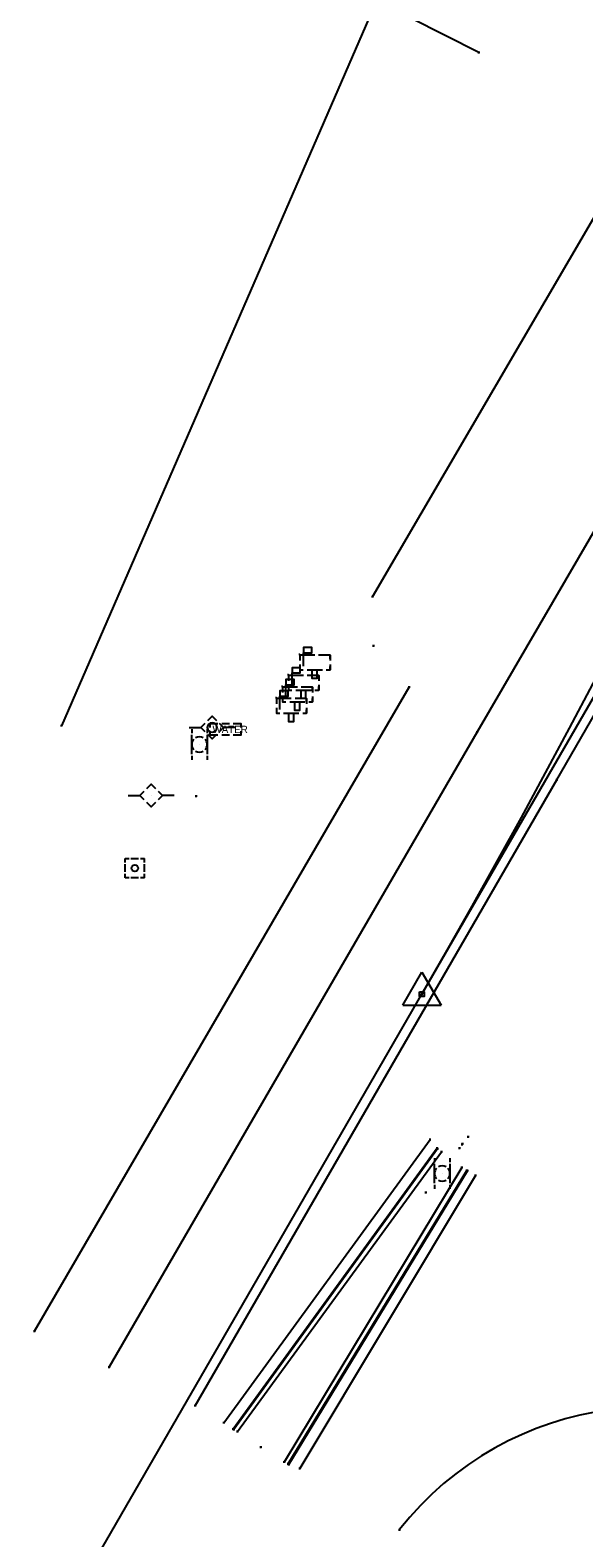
# Model space of a CAD drawing. Extents: x 1954856 to 2011933, y 399149 to 426294.
# Drawn here: x 2006044 to 2006116.2, y 401293.2 to 401490.1 of the extents above; entities that cross this region are included whole.
import ezdxf

# ---------------------------------------------------------------- set-up
doc = ezdxf.new("R2010")
doc.units = 0
for name, color, linetype in [('BaselineSurvey', 7, 'Continuous'), ('CGBack_ep', 7, 'Continuous'), ('CGep_ep', 7, 'Continuous'), ('CGFace_ep', 7, 'Continuous'), ('DelineatorPost_ep', 7, 'Continuous'), ('Driveway_ep', 7, 'Continuous'), ('Fence_ep', 7, 'Continuous'), ('Mailbox_ep', 7, 'Continuous'), ('MeterWater_ep', 7, 'Continuous'), ('MonumentNL_ep', 7, 'Continuous'), ('PavtAsphalt_ep', 7, 'Continuous'), ('PMRK_ep', 7, 'Continuous'), ('PointLocator_ep', 7, 'Continuous'), ('PoleElec_ep', 7, 'Continuous'), ('PoleShared_ep', 7, 'Continuous'), ('ShldrPaved_ep', 7, 'Continuous'), ('TelePed_ep', 7, 'Continuous')]:
    doc.layers.add(name, color=color, linetype=linetype)

# ---------------------------------------------------------------- blocks, each defined once
blk = doc.blocks.new('SURVPN-CROSS-')
at = {"layer": 'PointLocator_ep'}
for p, q in [((0.125, 0), (-0.125, 0)), ((0, -0.125), (0, 0.125)), ((0, 0), (0, 0))]:
    blk.add_line(p, q, dxfattribs=at)

msp = doc.modelspace()

# ---------------------------------------------------------------- linework, layer by layer
at = {"layer": 'BaselineSurvey'}
msp.add_line((2004815.66, 399148.96), (2006095.1, 401364.22), dxfattribs=at)
msp.add_line((2004815.66, 399148.96), (2006095.1, 401364.22), dxfattribs=at)
msp.add_lwpolyline([(2006095.1, 401364.22), (2006751.44, 402500.64), (2007687.69, 404121.69)], dxfattribs=at)
msp.add_arc((2005102.8, 401937.33), 1145.91, 329.99111, 11.93882, dxfattribs=at)
msp.add_arc((2005102.8, 401937.33), 1145.91, 329.99111, 11.93882, dxfattribs=at)
at = {"layer": 'CGBack_ep'}
for p, q in [((2006071.03, 401307.12), (2006097.64, 401343.62)), ((2006100.32, 401341.58), (2006077.12, 401303.14))]:
    msp.add_line(p, q, dxfattribs=at)
at = {"layer": 'CGep_ep'}
for p, q in [((2006097.07, 401344.11), (2006070.46, 401307.45)), ((2006077.75, 401302.84), (2006101.04, 401341.18))]:
    msp.add_line(p, q, dxfattribs=at)
at = {"layer": 'CGFace_ep'}
for p, q in [((2006097.12, 401344.03), (2006070.54, 401307.39)), ((2006077.66, 401302.89), (2006100.94, 401341.2))]:
    msp.add_line(p, q, dxfattribs=at)
at = {"layer": 'DelineatorPost_ep'}
for p, q in [((2006065.07, 401398.82), (2006065.07, 401398.32)), ((2006065.07, 401395.57), (2006065.07, 401398.07)), ((2006067.07, 401398.82), (2006067.07, 401398.32)), ((2006067.07, 401398.07), (2006067.07, 401395.57)), ((2006066.07, 401396.82), (2006066.07, 401396.82)), ((2006065.07, 401395.32), (2006065.07, 401394.82)), ((2006067.07, 401395.32), (2006067.07, 401394.82)), ((2006096.74, 401342.81), (2006096.74, 401342.31)), ((2006098.74, 401342.81), (2006098.74, 401342.31)), ((2006096.74, 401339.56), (2006096.74, 401342.06)), ((2006097.74, 401340.81), (2006097.74, 401340.81)), ((2006098.74, 401342.06), (2006098.74, 401339.56)), ((2006096.74, 401339.31), (2006096.74, 401338.81)), ((2006098.74, 401339.31), (2006098.74, 401338.81))]:
    msp.add_line(p, q, dxfattribs=at)
for centre, start, end in [((2006066.07, 401396.82), 60, 120), ((2006066.07, 401396.82), 138.5904, 221.4096), ((2006066.07, 401396.82), 240, 300), ((2006066.07, 401396.82), 318.5904, 41.4096), ((2006097.74, 401340.81), 138.5904, 221.4096), ((2006097.74, 401340.81), 60, 120), ((2006097.74, 401340.81), 318.5904, 41.4096), ((2006097.74, 401340.81), 240, 300)]:
    msp.add_arc(centre, 1, start, end, dxfattribs=at)
at = {"layer": 'Driveway_ep'}
msp.add_line((2006088.65, 401416.12), (2006131.95, 401490.32), dxfattribs=at)
at = {"layer": 'Fence_ep'}
msp.add_lwpolyline([(2006102.53, 401487.15), (2006089.17, 401493.91), (2006048.05, 401399.27)], dxfattribs=at)
at = {"layer": 'Mailbox_ep'}
for p, q in [((2006079.16, 401408.47), (2006079.16, 401407.77)), ((2006081.11, 401408.47), (2006079.16, 401408.47)), ((2006079.63, 401407.06), (2006079.63, 401408.79)), ((2006079.63, 401408.79), (2006080.61, 401408.79)), ((2006083.11, 401408.47), (2006083.11, 401407.77)), ((2006077.69, 401405.84), (2006077.69, 401405.13)), ((2006079.64, 401405.84), (2006077.69, 401405.84)), ((2006078.15, 401404.42), (2006078.15, 401406.16)), ((2006078.15, 401406.16), (2006079.14, 401406.16)), ((2006080.11, 401406.56), (2006080.61, 401406.56)), ((2006080.61, 401406.56), (2006082.11, 401406.56)), ((2006081.64, 401405.84), (2006081.64, 401405.13)), ((2006083.11, 401407.27), (2006083.11, 401406.56)), ((2006076.89, 401404.3), (2006076.89, 401403.6)), ((2006078.84, 401404.3), (2006076.89, 401404.3)), ((2006077.35, 401402.89), (2006077.35, 401404.62)), ((2006077.35, 401404.62), (2006078.34, 401404.62)), ((2006078.64, 401403.92), (2006079.14, 401403.92)), ((2006079.14, 401403.92), (2006080.64, 401403.92)), ((2006080.84, 401404.3), (2006080.84, 401403.6)), ((2006081.1, 401405.48), (2006081.1, 401405.48)), ((2006081.64, 401404.63), (2006081.64, 401403.92)), ((2006076.1, 401402.82), (2006076.1, 401402.11)), ((2006078.05, 401402.82), (2006076.1, 401402.82)), ((2006076.56, 401401.4), (2006076.56, 401403.14)), ((2006076.56, 401403.14), (2006077.55, 401403.14)), ((2006077.84, 401402.39), (2006078.34, 401402.39)), ((2006078.34, 401402.39), (2006079.84, 401402.39)), ((2006079.62, 401402.85), (2006079.62, 401402.85)), ((2006080.05, 401402.82), (2006080.05, 401402.11)), ((2006080.84, 401403.1), (2006080.84, 401402.39)), ((2006077.05, 401400.91), (2006077.55, 401400.91)), ((2006077.55, 401400.91), (2006079.05, 401400.91)), ((2006078.04, 401399.83), (2006078.04, 401399.83)), ((2006078.82, 401401.31), (2006078.82, 401401.31)), ((2006080.05, 401401.61), (2006080.05, 401400.91))]:
    msp.add_line(p, q, dxfattribs=at)
for points in [[(2006079.05, 401408.6), (2006079.13, 401408.6), (2006079.16, 401408.42)], [(2006080.61, 401409.48), (2006079.63, 401409.48), (2006079.63, 401408.79)], [(2006080.61, 401408.79), (2006080.71, 401408.79), (2006080.71, 401409.48), (2006080.61, 401409.48)], [(2006083.11, 401408.01), (2006083.11, 401408.47), (2006081.61, 401408.47)], [(2006077.57, 401405.96), (2006077.65, 401405.96), (2006077.69, 401405.79)], [(2006079.14, 401406.85), (2006078.15, 401406.85), (2006078.15, 401406.16)], [(2006079.14, 401406.16), (2006079.23, 401406.16), (2006079.23, 401406.85), (2006079.14, 401406.85)], [(2006079.16, 401407.27), (2006079.16, 401406.56), (2006079.61, 401406.56)], [(2006081.64, 401405.38), (2006081.64, 401405.84), (2006080.14, 401405.84)], [(2006080.75, 401406.56), (2006080.75, 401405.48), (2006081.44, 401405.48), (2006081.44, 401406.56)], [(2006082.61, 401406.56), (2006083.11, 401406.56), (2006083.11, 401407.01)], [(2006077.55, 401403.83), (2006076.56, 401403.83), (2006076.56, 401403.14)], [(2006076.78, 401404.43), (2006076.86, 401404.43), (2006076.89, 401404.25)], [(2006078.34, 401405.31), (2006077.35, 401405.31), (2006077.35, 401404.62)], [(2006077.55, 401403.14), (2006077.64, 401403.14), (2006077.64, 401403.83), (2006077.55, 401403.83)], [(2006077.69, 401404.63), (2006077.69, 401403.92), (2006078.14, 401403.92)], [(2006078.34, 401404.62), (2006078.43, 401404.62), (2006078.43, 401405.31), (2006078.34, 401405.31)], [(2006079.28, 401403.92), (2006079.28, 401402.85), (2006079.97, 401402.85), (2006079.97, 401403.92)], [(2006080.84, 401403.84), (2006080.84, 401404.3), (2006079.34, 401404.3)], [(2006081.14, 401403.92), (2006081.64, 401403.92), (2006081.64, 401404.38)], [(2006075.99, 401402.95), (2006076.07, 401402.95), (2006076.1, 401402.77)], [(2006076.89, 401403.1), (2006076.89, 401402.39), (2006077.34, 401402.39)], [(2006078.48, 401402.39), (2006078.48, 401401.31), (2006079.17, 401401.31), (2006079.17, 401402.39)], [(2006080.05, 401402.36), (2006080.05, 401402.82), (2006078.55, 401402.82)], [(2006080.34, 401402.39), (2006080.84, 401402.39), (2006080.84, 401402.84)], [(2006076.1, 401401.61), (2006076.1, 401400.91), (2006076.55, 401400.91)], [(2006077.69, 401400.91), (2006077.69, 401399.83), (2006078.38, 401399.83), (2006078.38, 401400.91)], [(2006079.55, 401400.91), (2006080.05, 401400.91), (2006080.05, 401401.36)]]:
    msp.add_lwpolyline(points, dxfattribs=at)
at = {"layer": 'MeterWater_ep'}
msp.add_line((2006069.47, 401398.79), (2006069.47, 401398.79), dxfattribs=at)
for points in [[(2006067.47, 401399.04), (2006067.47, 401399.54), (2006068.47, 401399.54)], [(2006068.47, 401398.04), (2006067.47, 401398.04), (2006067.47, 401398.54)], [(2006068.97, 401399.54), (2006069.97, 401399.54)], [(2006069.97, 401398.04), (2006068.97, 401398.04)], [(2006070.47, 401399.54), (2006071.47, 401399.54), (2006071.47, 401399.04)], [(2006071.47, 401398.54), (2006071.47, 401398.04), (2006070.47, 401398.04)]]:
    msp.add_lwpolyline(points, dxfattribs=at)
at = {"layer": 'MonumentNL_ep'}
for p, q in [((2006092.59, 401362.78), (2006095.09, 401367.11)), ((2006095.09, 401367.11), (2006097.59, 401362.78)), ((2006092.59, 401362.78), (2006097.59, 401362.78)), ((2006095.09, 401364.22), (2006095.09, 401364.22))]:
    msp.add_line(p, q, dxfattribs=at)
msp.add_lwpolyline([(2006094.79, 401364.52), (2006095.39, 401364.52), (2006095.39, 401363.92), (2006094.79, 401363.92)], close=True, dxfattribs=at)
at = {"layer": 'PavtAsphalt_ep'}
for p, q in [((2006069.24, 401308.28), (2006096.16, 401345.25)), ((2006102.07, 401340.55), (2006079.15, 401302.29))]:
    msp.add_line(p, q, dxfattribs=at)
msp.add_lwpolyline([(2006054.29, 401315.52), (2006102.3, 401398.42), (2006149.97, 401480.37), (2006190, 401548.85), (2006229.29, 401617.08), (2006237.48, 401631.06)], dxfattribs=at)
msp.add_arc((2006125.11, 401268.41), 41.91, 53.2441, 141.8601, dxfattribs=at)
at = {"layer": 'PMRK_ep'}
msp.add_lwpolyline([(2006065.53, 401310.49), (2006112.72, 401392.19), (2006160.25, 401474.61), (2006200.54, 401543.09), (2006235.51, 401603.67)], dxfattribs=at)
at = {"layer": 'PointLocator_ep'}
for p, q in [((2006102.65, 401487.15), (2006102.4, 401487.15)), ((2006102.53, 401487.02), (2006102.53, 401487.27)), ((2006102.53, 401487.15), (2006102.53, 401487.15)), ((2006088.77, 401416.12), (2006088.52, 401416.12)), ((2006088.65, 401415.99), (2006088.65, 401416.24)), ((2006088.65, 401416.12), (2006088.65, 401416.12)), ((2006088.92, 401409.7), (2006088.67, 401409.7)), ((2006088.79, 401409.57), (2006088.79, 401409.82)), ((2006088.79, 401409.7), (2006088.79, 401409.7)), ((2006093.57, 401404.31), (2006093.32, 401404.31)), ((2006093.44, 401404.19), (2006093.44, 401404.44)), ((2006093.44, 401404.31), (2006093.44, 401404.31)), ((2006048.17, 401399.27), (2006047.92, 401399.27)), ((2006048.05, 401399.15), (2006048.05, 401399.4)), ((2006048.05, 401399.27), (2006048.05, 401399.27)), ((2006102.42, 401398.42), (2006102.17, 401398.42)), ((2006102.3, 401398.3), (2006102.3, 401398.55)), ((2006102.3, 401398.42), (2006102.3, 401398.42)), ((2006112.85, 401392.19), (2006112.6, 401392.19)), ((2006112.72, 401392.07), (2006112.72, 401392.32)), ((2006112.72, 401392.19), (2006112.72, 401392.19)), ((2006065.75, 401390.08), (2006065.5, 401390.08)), ((2006065.62, 401389.96), (2006065.62, 401390.21)), ((2006065.62, 401390.08), (2006065.62, 401390.08)), ((2006095.1, 401364.1), (2006095.1, 401364.35)), ((2006095.22, 401364.22), (2006094.97, 401364.22)), ((2006095.1, 401364.22), (2006095.1, 401364.22)), ((2006096.28, 401345.25), (2006096.03, 401345.25)), ((2006096.16, 401345.13), (2006096.16, 401345.38)), ((2006096.16, 401345.25), (2006096.16, 401345.25)), ((2006100.51, 401344.69), (2006100.26, 401344.69)), ((2006100.39, 401344.56), (2006100.39, 401344.81)), ((2006100.39, 401344.69), (2006100.39, 401344.69)), ((2006101.26, 401345.6), (2006101.01, 401345.6)), ((2006101.13, 401345.48), (2006101.13, 401345.73)), ((2006101.13, 401345.6), (2006101.13, 401345.6)), ((2006097.19, 401344.11), (2006096.94, 401344.11)), ((2006097.07, 401343.99), (2006097.07, 401344.24)), ((2006097.07, 401344.11), (2006097.07, 401344.11)), ((2006097.76, 401343.62), (2006097.51, 401343.62)), ((2006097.64, 401343.5), (2006097.64, 401343.75)), ((2006097.64, 401343.62), (2006097.64, 401343.62)), ((2006100.11, 401344.12), (2006099.86, 401344.12)), ((2006099.99, 401344), (2006099.99, 401344.25)), ((2006099.99, 401344.12), (2006099.99, 401344.12)), ((2006100.44, 401341.58), (2006100.19, 401341.58)), ((2006100.32, 401341.45), (2006100.32, 401341.7)), ((2006100.32, 401341.58), (2006100.32, 401341.58)), ((2006101.17, 401341.18), (2006100.92, 401341.18)), ((2006101.04, 401341.06), (2006101.04, 401341.31)), ((2006101.04, 401341.18), (2006101.04, 401341.18)), ((2006102.2, 401340.55), (2006101.95, 401340.55)), ((2006102.07, 401340.42), (2006102.07, 401340.67)), ((2006102.07, 401340.55), (2006102.07, 401340.55)), ((2006095.73, 401338.33), (2006095.48, 401338.33)), ((2006095.6, 401338.21), (2006095.6, 401338.46)), ((2006095.6, 401338.33), (2006095.6, 401338.33)), ((2006044.68, 401320.23), (2006044.43, 401320.23)), ((2006044.56, 401320.11), (2006044.56, 401320.36)), ((2006044.56, 401320.23), (2006044.56, 401320.23)), ((2006054.41, 401315.52), (2006054.16, 401315.52)), ((2006054.29, 401315.4), (2006054.29, 401315.65)), ((2006054.29, 401315.52), (2006054.29, 401315.52)), ((2006065.66, 401310.49), (2006065.41, 401310.49)), ((2006065.53, 401310.37), (2006065.53, 401310.62)), ((2006065.53, 401310.49), (2006065.53, 401310.49)), ((2006069.36, 401308.28), (2006069.11, 401308.28)), ((2006069.24, 401308.15), (2006069.24, 401308.4)), ((2006069.24, 401308.28), (2006069.24, 401308.28)), ((2006070.59, 401307.45), (2006070.34, 401307.45)), ((2006070.46, 401307.33), (2006070.46, 401307.58)), ((2006070.46, 401307.45), (2006070.46, 401307.45)), ((2006071.03, 401306.99), (2006071.03, 401307.24)), ((2006071.15, 401307.12), (2006070.9, 401307.12)), ((2006071.03, 401307.12), (2006071.03, 401307.12)), ((2006074.21, 401305.09), (2006073.96, 401305.09)), ((2006074.08, 401304.97), (2006074.08, 401305.22)), ((2006074.08, 401305.09), (2006074.08, 401305.09)), ((2006077.25, 401303.14), (2006077, 401303.14)), ((2006077.12, 401303.02), (2006077.12, 401303.27)), ((2006077.12, 401303.14), (2006077.12, 401303.14)), ((2006077.88, 401302.84), (2006077.62, 401302.84)), ((2006077.75, 401302.71), (2006077.75, 401302.96)), ((2006077.75, 401302.84), (2006077.75, 401302.84)), ((2006079.27, 401302.29), (2006079.02, 401302.29)), ((2006079.15, 401302.17), (2006079.15, 401302.42)), ((2006079.15, 401302.29), (2006079.15, 401302.29)), ((2006092.28, 401294.3), (2006092.03, 401294.3)), ((2006092.15, 401294.17), (2006092.15, 401294.42)), ((2006092.15, 401294.3), (2006092.15, 401294.3))]:
    msp.add_line(p, q, dxfattribs=at)
at = {"layer": 'PoleElec_ep'}
for p, q in [((2006056.77, 401390.15), (2006058.27, 401390.15)), ((2006058.27, 401390.15), (2006058.84, 401390.72)), ((2006058.84, 401389.58), (2006058.27, 401390.15)), ((2006059.76, 401390.15), (2006059.76, 401390.15)), ((2006062.75, 401390.15), (2006061.25, 401390.15))]:
    msp.add_line(p, q, dxfattribs=at)
for points in [[(2006059.19, 401391.07), (2006059.76, 401391.64), (2006060.33, 401391.07)], [(2006060.68, 401390.72), (2006061.25, 401390.15), (2006060.68, 401389.58)], [(2006060.33, 401389.23), (2006059.76, 401388.66), (2006059.19, 401389.23)]]:
    msp.add_lwpolyline(points, dxfattribs=at)
at = {"layer": 'PoleShared_ep'}
for p, q in [((2006064.74, 401399.04), (2006066.24, 401399.04)), ((2006066.24, 401399.04), (2006066.8, 401399.6)), ((2006066.8, 401398.48), (2006066.24, 401399.04)), ((2006067.72, 401399.04), (2006067.72, 401399.04)), ((2006070.71, 401399.04), (2006069.21, 401399.04))]:
    msp.add_line(p, q, dxfattribs=at)
for points in [[(2006067.16, 401399.96), (2006067.72, 401400.53), (2006068.29, 401399.96)], [(2006068.29, 401398.12), (2006067.72, 401397.55), (2006067.16, 401398.12)], [(2006068.65, 401399.6), (2006069.21, 401399.04), (2006068.64, 401398.47)]]:
    msp.add_lwpolyline(points, dxfattribs=at)
for start, end in [(90, 270), (270, 90)]:
    msp.add_arc((2006067.72, 401399.04), 0.625, start, end, dxfattribs=at)
at = {"layer": 'ShldrPaved_ep'}
msp.add_lwpolyline([(2006044.56, 401320.23), (2006093.44, 401404.31)], dxfattribs=at)
at = {"layer": 'TelePed_ep'}
for p, q in [((2006056.38, 401381.93), (2006056.88, 401381.93)), ((2006056.38, 401381.43), (2006056.38, 401381.93)), ((2006056.38, 401380.18), (2006056.38, 401381.18)), ((2006057.13, 401381.93), (2006058.13, 401381.93)), ((2006057.63, 401380.68), (2006057.63, 401380.68)), ((2006058.38, 401381.93), (2006058.88, 401381.93)), ((2006058.88, 401381.43), (2006058.88, 401381.93)), ((2006058.88, 401380.18), (2006058.88, 401381.18)), ((2006056.38, 401379.43), (2006056.38, 401379.93)), ((2006056.88, 401379.43), (2006056.38, 401379.43)), ((2006058.13, 401379.43), (2006057.13, 401379.43)), ((2006058.88, 401379.43), (2006058.38, 401379.43)), ((2006058.88, 401379.43), (2006058.88, 401379.93))]:
    msp.add_line(p, q, dxfattribs=at)
msp.add_circle((2006057.63, 401380.68), 0.438, dxfattribs=at)

# ---------------------------------------------------------------- block references
at = {"layer": 'PointLocator_ep'}
for p in [(2006100.33, 401344.6), (2006097.12, 401344.03), (2006100.94, 401341.2), (2006070.54, 401307.39), (2006077.66, 401302.89)]:
    msp.add_blockref('SURVPN-CROSS-', p, dxfattribs=at)

# ---------------------------------------------------------------- texts
at = {"layer": 'MeterWater_ep'}
msp.add_text('WATER', height=0.95, dxfattribs=at).set_placement((2006067.78, 401398.32))

doc.saveas('drawing.dxf')
